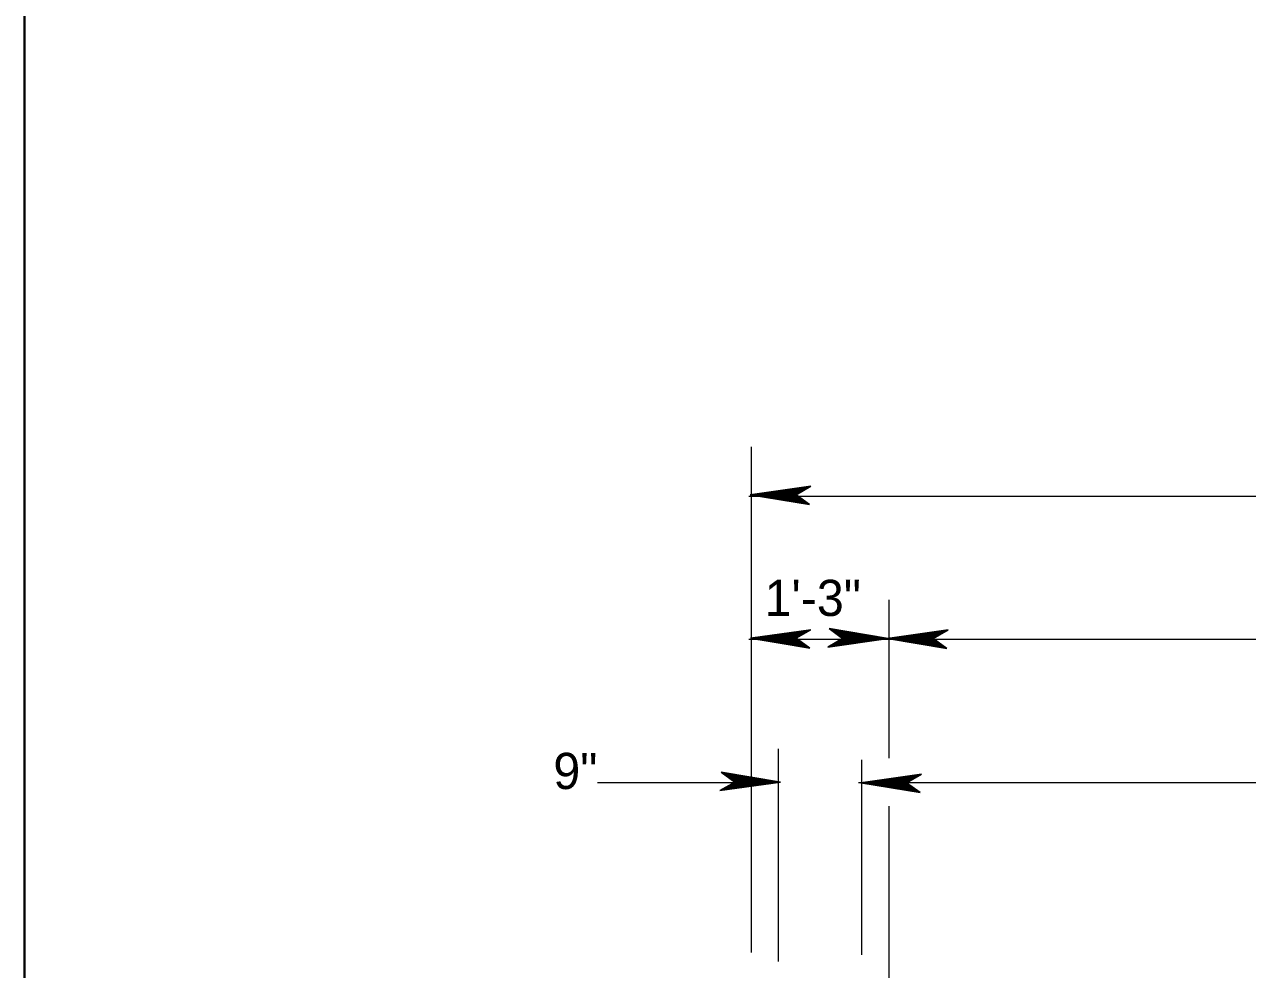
# Model space of a CAD drawing. Extents: x 144 to 252, y 360 to 425.
# Drawn here: x 149.81 to 160.9, y 379.97 to 388.54 of the extents above; entities that cross this region are included whole.
import ezdxf
from ezdxf.enums import TextEntityAlignment as Align

# ---------------------------------------------------------------- set-up
doc = ezdxf.new("R2010")
doc.units = 0
doc.header["$LTSCALE"] = 0.13
for name, color, linetype, lineweight in [('1', 7, 'Continuous', 40), ('16', 7, 'Continuous', 13), ('3', 7, 'Continuous', 13)]:
    doc.layers.add(name, color=color, linetype=linetype, lineweight=lineweight)

msp = doc.modelspace()

# ---------------------------------------------------------------- linework, layer by layer
at = {"layer": '1', "lineweight": 13}
for p, q in [((156.4041, 380.1236), (156.4041, 382.9759)), ((157.4041, 381.1957), (157.4041, 381.871)), ((156.6476, 381.6627), (155.0067, 381.6627)), ((177.4166, 381.6627), (157.3739, 381.6627)), ((157.4041, 380.7103), (157.4041, 381.1957)), ((157.4041, 380.1021), (157.4041, 381.0482))]:
    msp.add_line(p, q, dxfattribs=at)
at = {"layer": '1'}
msp.add_lwpolyline([(250.3172, 361.9183), (250.3172, 423.9913), (149.8112, 423.9913), (149.8112, 361.9183), (230.3642, 361.9183)], dxfattribs=at)
at = {"layer": '3'}
for p, q in [((156.4041, 382.7622), (156.4041, 384.7079)), ((156.3791, 384.2597), (180.3798, 384.2597)), ((156.9406, 384.3518), (156.3918, 384.2741)), ((156.3918, 384.2741), (156.9295, 384.1848)), ((156.8072, 384.2741), (156.3918, 384.2741)), ((156.9346, 384.3483), (156.4062, 384.2734)), ((156.4062, 384.2734), (156.9262, 384.1872)), ((156.9311, 384.3463), (156.4171, 384.2734)), ((156.4171, 384.2734), (156.923, 384.1895)), ((156.9265, 384.3437), (156.4315, 384.2734)), ((156.4315, 384.2734), (156.9187, 384.1927)), ((156.9224, 384.3413), (156.4442, 384.2734)), ((156.9224, 384.3413), (156.4442, 384.2734)), ((156.4442, 384.2734), (156.915, 384.1953)), ((156.9187, 384.3391), (156.4556, 384.2734)), ((156.4556, 384.2734), (156.9117, 384.1977)), ((156.9142, 384.3364), (156.47, 384.2734)), ((156.47, 384.2734), (156.9074, 384.2009)), ((156.9101, 384.334), (156.4827, 384.2734)), ((156.4827, 384.2734), (156.9037, 384.2037)), ((156.9057, 384.3315), (156.4965, 384.2734)), ((156.4965, 384.2734), (156.8996, 384.2066)), ((156.9013, 384.3289), (156.5103, 384.2734)), ((156.5103, 384.2734), (156.8955, 384.2096)), ((156.897, 384.3264), (156.5236, 384.2734)), ((156.5236, 384.2734), (156.8916, 384.2124)), ((156.8925, 384.3237), (156.5375, 384.2734)), ((156.5375, 384.2734), (156.8875, 384.2154)), ((156.8885, 384.3215), (156.5501, 384.2734)), ((156.5501, 384.2734), (156.8837, 384.2181)), ((156.8847, 384.3193), (156.5615, 384.2734)), ((156.5615, 384.2734), (156.8803, 384.2206)), ((156.8798, 384.3164), (156.5772, 384.2734)), ((156.5772, 384.2734), (156.8757, 384.2239)), ((156.8753, 384.3137), (156.591, 384.2734)), ((156.591, 384.2734), (156.8717, 384.2269)), ((156.8682, 384.3096), (156.609, 384.2729)), ((156.609, 384.2729), (156.8674, 384.23)), ((156.8713, 384.3115), (156.6106, 384.2745)), ((156.8637, 384.307), (156.6229, 384.2729)), ((156.6229, 384.2729), (156.8632, 384.233)), ((156.8595, 384.3045), (156.6361, 384.2729)), ((156.6361, 384.2729), (156.8594, 384.2358)), ((156.858, 384.3037), (156.6452, 384.2734)), ((156.6452, 384.2734), (156.8557, 384.2386)), ((156.8541, 384.3014), (156.6572, 384.2734)), ((156.6572, 384.2734), (156.8521, 384.2412)), ((156.8497, 384.2987), (156.671, 384.2734)), ((156.671, 384.2734), (156.848, 384.2442)), ((156.8447, 384.2959), (156.6867, 384.2734)), ((156.6867, 384.2734), (156.8433, 384.2474)), ((156.8406, 384.2935), (156.6993, 384.2734)), ((156.6993, 384.2734), (156.8397, 384.2502)), ((156.8363, 384.291), (156.7125, 384.2734)), ((156.7125, 384.2734), (156.8357, 384.253)), ((156.8325, 384.2887), (156.7245, 384.2734)), ((156.7245, 384.2734), (156.8322, 384.2557)), ((156.8278, 384.2861), (156.739, 384.2734)), ((156.739, 384.2734), (156.8279, 384.2587)), ((156.8234, 384.2835), (156.7528, 384.2734)), ((156.7528, 384.2734), (156.8237, 384.2617)), ((156.8193, 384.2812), (156.7655, 384.2734)), ((156.7655, 384.2734), (156.8201, 384.2644)), ((156.7788, 384.2734), (156.8162, 384.2672)), ((156.8141, 384.2781), (156.789, 384.2745)), ((156.8114, 384.2765), (156.7902, 384.2734)), ((156.7902, 384.2734), (156.8127, 384.2697)), ((156.8003, 384.2734), (156.8098, 384.2719)), ((156.807, 384.2739), (156.9406, 384.3518)), ((156.9295, 384.1848), (156.807, 384.2739)), ((156.4041, 382.7622), (156.4041, 383.3206)), ((157.6499, 382.7622), (157.6499, 383.3206)), ((156.9417, 383.0497), (156.393, 382.972)), ((156.9357, 383.0462), (156.4074, 382.9713)), ((156.9322, 383.0442), (156.4183, 382.9713)), ((156.9277, 383.0416), (156.4327, 382.9713)), ((156.9236, 383.0392), (156.4454, 382.9713)), ((156.9236, 383.0392), (156.4454, 382.9713)), ((156.9199, 383.037), (156.4567, 382.9713)), ((156.9153, 383.0343), (156.4712, 382.9713)), ((156.9112, 383.0319), (156.4839, 382.9713)), ((156.9068, 383.0294), (156.4977, 382.9713)), ((156.9024, 383.0268), (156.5115, 382.9713)), ((156.8082, 382.9718), (156.9417, 383.0497)), ((157.6437, 382.9702), (157.1061, 383.0595)), ((157.1061, 383.0595), (157.2286, 382.9704)), ((157.6293, 382.9709), (157.1093, 383.0572)), ((157.6185, 382.9709), (157.1126, 383.0548)), ((157.6041, 382.9709), (157.1168, 383.0517)), ((157.5913, 382.9709), (157.1206, 383.049)), ((157.58, 382.9709), (157.1239, 383.0466)), ((157.5656, 382.9709), (157.1282, 383.0434)), ((157.5528, 382.9709), (157.1319, 383.0407)), ((157.5391, 382.9709), (157.136, 383.0377)), ((157.5252, 382.9709), (157.1401, 383.0347)), ((157.512, 382.9709), (157.144, 383.0319)), ((157.4981, 382.9709), (157.1481, 383.0289)), ((157.4855, 382.9709), (157.1518, 383.0263)), ((158.1851, 383.048), (157.6363, 382.9702)), ((158.1791, 383.0445), (157.6507, 382.9696)), ((158.1756, 383.0425), (157.6616, 382.9696)), ((158.171, 383.0398), (157.676, 382.9696)), ((158.1669, 383.0374), (157.6887, 382.9696)), ((158.1669, 383.0374), (157.6887, 382.9696)), ((158.1633, 383.0352), (157.7001, 382.9696)), ((158.1587, 383.0326), (157.7145, 382.9696)), ((158.1546, 383.0302), (157.7272, 382.9696)), ((158.1502, 383.0277), (157.741, 382.9696)), ((158.0515, 382.9701), (158.1851, 383.048)), ((156.38, 382.9646), (179.0847, 382.9646)), ((156.393, 382.972), (156.9307, 382.8827)), ((156.8084, 382.972), (156.393, 382.972)), ((156.4074, 382.9713), (156.9274, 382.8851)), ((156.4183, 382.9713), (156.9242, 382.8874)), ((156.4327, 382.9713), (156.9199, 382.8906)), ((156.4454, 382.9713), (156.9162, 382.8932)), ((156.4567, 382.9713), (156.9128, 382.8957)), ((156.4712, 382.9713), (156.9086, 382.8988)), ((156.4839, 382.9713), (156.9048, 382.9016)), ((156.4977, 382.9713), (156.9007, 382.9045)), ((156.5115, 382.9713), (156.8967, 382.9075)), ((156.8982, 383.0243), (156.5247, 382.9713)), ((156.5247, 382.9713), (156.8928, 382.9103)), ((156.8937, 383.0217), (156.5387, 382.9713)), ((156.5387, 382.9713), (156.8887, 382.9133)), ((156.8897, 383.0194), (156.5512, 382.9713)), ((156.5512, 382.9713), (156.8849, 382.916)), ((156.8859, 383.0172), (156.5627, 382.9713)), ((156.5627, 382.9713), (156.8815, 382.9185)), ((156.8809, 383.0143), (156.5783, 382.9713)), ((156.5783, 382.9713), (156.8769, 382.9218)), ((156.8765, 383.0117), (156.5922, 382.9713)), ((156.5922, 382.9713), (156.8728, 382.9248)), ((156.8693, 383.0075), (156.6102, 382.9708)), ((156.6102, 382.9708), (156.8686, 382.9279)), ((156.8725, 383.0094), (156.6118, 382.9724)), ((156.8649, 383.0049), (156.6241, 382.9708)), ((156.6241, 382.9708), (156.8644, 382.9309)), ((156.8607, 383.0024), (156.6372, 382.9708)), ((156.6372, 382.9708), (156.8606, 382.9337)), ((156.8592, 383.0016), (156.6463, 382.9713)), ((156.6463, 382.9713), (156.8568, 382.9365)), ((156.8552, 382.9993), (156.6583, 382.9713)), ((156.6583, 382.9713), (156.8533, 382.9391)), ((156.8508, 382.9967), (156.6722, 382.9713)), ((156.6722, 382.9713), (156.8492, 382.9421)), ((156.8458, 382.9938), (156.6878, 382.9713)), ((156.6878, 382.9713), (156.8445, 382.9453)), ((156.8417, 382.9914), (156.7004, 382.9713)), ((156.7004, 382.9713), (156.8408, 382.9481)), ((156.8375, 382.9889), (156.7137, 382.9713)), ((156.7137, 382.9713), (156.8369, 382.9509)), ((156.8337, 382.9867), (156.7257, 382.9713)), ((156.7257, 382.9713), (156.8333, 382.9536)), ((156.829, 382.984), (156.7402, 382.9713)), ((156.7402, 382.9713), (156.8291, 382.9566)), ((156.8246, 382.9814), (156.754, 382.9713)), ((156.754, 382.9713), (156.8249, 382.9596)), ((156.8205, 382.9791), (156.7667, 382.9713)), ((156.7667, 382.9713), (156.8212, 382.9623)), ((156.7799, 382.9713), (156.8173, 382.9652)), ((156.8152, 382.976), (156.7902, 382.9724)), ((156.8126, 382.9744), (156.7913, 382.9713)), ((156.7913, 382.9713), (156.8139, 382.9676)), ((156.8015, 382.9713), (156.8109, 382.9698)), ((156.9307, 382.8827), (156.8082, 382.9718)), ((157.2286, 382.9704), (157.095, 382.8925)), ((157.095, 382.8925), (157.6437, 382.9702)), ((157.101, 382.896), (157.6293, 382.9709)), ((157.1045, 382.898), (157.6185, 382.9709)), ((157.1091, 382.9007), (157.6041, 382.9709)), ((157.1132, 382.9031), (157.5913, 382.9709)), ((157.1132, 382.9031), (157.5913, 382.9709)), ((157.1168, 382.9052), (157.58, 382.9709)), ((157.1214, 382.9079), (157.5656, 382.9709)), ((157.1255, 382.9103), (157.5528, 382.9709)), ((157.1299, 382.9128), (157.5391, 382.9709)), ((157.1343, 382.9154), (157.5252, 382.9709)), ((157.1386, 382.9179), (157.512, 382.9709)), ((157.1431, 382.9206), (157.4981, 382.9709)), ((157.1471, 382.9228), (157.4855, 382.9709)), ((157.1508, 382.9251), (157.4741, 382.9709)), ((157.4741, 382.9709), (157.1552, 383.0238)), ((157.1558, 382.9279), (157.4584, 382.9709)), ((157.4584, 382.9709), (157.1598, 383.0204)), ((157.1602, 382.9306), (157.4446, 382.9709)), ((157.4446, 382.9709), (157.1639, 383.0174)), ((157.1642, 382.9328), (157.425, 382.9698)), ((157.1674, 382.9348), (157.4266, 382.9714)), ((157.4266, 382.9714), (157.1682, 383.0143)), ((157.1718, 382.9373), (157.4127, 382.9714)), ((157.4127, 382.9714), (157.1723, 383.0113)), ((157.1761, 382.9398), (157.3995, 382.9714)), ((157.3995, 382.9714), (157.1762, 383.0085)), ((157.1776, 382.9407), (157.3904, 382.9709)), ((157.3904, 382.9709), (157.1799, 383.0057)), ((157.1815, 382.9429), (157.3784, 382.9709)), ((157.3784, 382.9709), (157.1835, 383.0032)), ((157.1859, 382.9456), (157.3646, 382.9709)), ((157.3646, 382.9709), (157.1876, 383.0002)), ((157.1909, 382.9484), (157.3489, 382.9709)), ((157.3489, 382.9709), (157.1923, 382.9969)), ((157.195, 382.9508), (157.3363, 382.9709)), ((157.3363, 382.9709), (157.1959, 382.9942)), ((157.1993, 382.9533), (157.3231, 382.9709)), ((157.3231, 382.9709), (157.1998, 382.9913)), ((157.2031, 382.9556), (157.3111, 382.9709)), ((157.3111, 382.9709), (157.2034, 382.9887)), ((157.2966, 382.9709), (157.2077, 382.9857)), ((157.2078, 382.9582), (157.2966, 382.9709)), ((157.2827, 382.9709), (157.2118, 382.9827)), ((157.2122, 382.9608), (157.2827, 382.9709)), ((157.2701, 382.9709), (157.2155, 382.9799)), ((157.2163, 382.9632), (157.2701, 382.9709)), ((157.2568, 382.9709), (157.2194, 382.9771)), ((157.2215, 382.9663), (157.2466, 382.9698)), ((157.2454, 382.9709), (157.2228, 382.9747)), ((157.2242, 382.9678), (157.2454, 382.9709)), ((157.2353, 382.9709), (157.2258, 382.9724)), ((157.2283, 382.9702), (157.6437, 382.9702)), ((157.6363, 382.9702), (158.174, 382.881)), ((158.0517, 382.9702), (157.6363, 382.9702)), ((157.6507, 382.9696), (158.1707, 382.8833)), ((157.6616, 382.9696), (158.1675, 382.8857)), ((157.676, 382.9696), (158.1633, 382.8888)), ((157.6887, 382.9696), (158.1595, 382.8915)), ((157.7001, 382.9696), (158.1562, 382.8939)), ((157.7145, 382.9696), (158.1519, 382.8971)), ((157.7272, 382.9696), (158.1482, 382.8998)), ((157.741, 382.9696), (158.1441, 382.9027)), ((158.1457, 383.0251), (157.7548, 382.9696)), ((157.7548, 382.9696), (158.14, 382.9058)), ((158.1415, 383.0226), (157.7681, 382.9696)), ((157.7681, 382.9696), (158.1361, 382.9086)), ((158.137, 383.0199), (157.782, 382.9696)), ((157.782, 382.9696), (158.132, 382.9116)), ((158.133, 383.0177), (157.7946, 382.9696)), ((157.7946, 382.9696), (158.1283, 382.9142)), ((158.1292, 383.0154), (157.806, 382.9696)), ((157.806, 382.9696), (158.1248, 382.9167)), ((158.1242, 383.0126), (157.8217, 382.9696)), ((157.8217, 382.9696), (158.1202, 382.9201)), ((158.1198, 383.0099), (157.8355, 382.9696)), ((157.8355, 382.9696), (158.1162, 382.9231)), ((158.1127, 383.0057), (157.8535, 382.9691)), ((157.8535, 382.9691), (158.1119, 382.9262)), ((158.1158, 383.0077), (157.8551, 382.9707)), ((158.1082, 383.0032), (157.8674, 382.9691)), ((157.8674, 382.9691), (158.1077, 382.9292)), ((158.104, 383.0007), (157.8806, 382.9691)), ((157.8806, 382.9691), (158.1039, 382.932)), ((158.1025, 382.9998), (157.8897, 382.9696)), ((157.8897, 382.9696), (158.1002, 382.9348)), ((158.0986, 382.9976), (157.9017, 382.9696)), ((157.9017, 382.9696), (158.0966, 382.9373)), ((158.0942, 382.9949), (157.9155, 382.9696)), ((157.9155, 382.9696), (158.0925, 382.9403)), ((158.0892, 382.9921), (157.9312, 382.9696)), ((157.9312, 382.9696), (158.0878, 382.9436)), ((158.0851, 382.9897), (157.9437, 382.9696)), ((157.9437, 382.9696), (158.0842, 382.9463)), ((158.0808, 382.9872), (157.957, 382.9696)), ((157.957, 382.9696), (158.0803, 382.9492)), ((158.077, 382.9849), (157.969, 382.9696)), ((157.969, 382.9696), (158.0767, 382.9518)), ((158.0723, 382.9822), (157.9835, 382.9696)), ((157.9835, 382.9696), (158.0724, 382.9548)), ((158.0679, 382.9797), (157.9973, 382.9696)), ((157.9973, 382.9696), (158.0683, 382.9578)), ((158.0638, 382.9773), (158.01, 382.9696)), ((158.01, 382.9696), (158.0646, 382.9606)), ((158.0232, 382.9696), (158.0607, 382.9634)), ((158.0586, 382.9742), (158.0335, 382.9707)), ((158.0559, 382.9727), (158.0347, 382.9696)), ((158.0347, 382.9696), (158.0572, 382.9658)), ((158.0448, 382.9696), (158.0542, 382.9681)), ((158.174, 382.881), (158.0515, 382.9701)), ((156.4041, 382.7622), (156.4041, 382.8667)), ((156.4041, 382.7137), (156.4041, 382.8667)), ((157.6499, 381.8838), (157.6499, 382.8667)), ((156.648, 380.0423), (156.648, 381.9688)), ((156.6659, 381.6682), (156.1283, 381.7574)), ((156.1283, 381.7574), (156.2507, 381.6683)), ((156.6515, 381.6688), (156.1315, 381.7551)), ((156.6407, 381.6688), (156.1347, 381.7527)), ((156.6262, 381.6688), (156.139, 381.7496)), ((156.6135, 381.6688), (156.1428, 381.7469)), ((156.6022, 381.6688), (156.1461, 381.7445)), ((156.5877, 381.6688), (156.1503, 381.7413)), ((156.575, 381.6688), (156.1541, 381.7386)), ((156.5613, 381.6688), (156.1582, 381.7357)), ((156.5474, 381.6688), (156.1623, 381.7327)), ((156.5342, 381.6688), (156.1662, 381.7298)), ((156.5203, 381.6688), (156.1702, 381.7268)), ((156.5077, 381.6688), (156.174, 381.7242)), ((156.4963, 381.6688), (156.1774, 381.7217)), ((156.4806, 381.6688), (156.182, 381.7183)), ((156.4667, 381.6688), (156.1861, 381.7153)), ((156.4487, 381.6693), (156.1903, 381.7122)), ((156.4348, 381.6693), (156.1945, 381.7092)), ((156.4217, 381.6693), (156.1983, 381.7064)), ((156.4126, 381.6688), (156.2021, 381.7037)), ((156.4006, 381.6688), (156.2057, 381.7011)), ((156.3868, 381.6688), (156.2097, 381.6981)), ((156.3711, 381.6688), (156.2144, 381.6948)), ((157.943, 381.7406), (157.3942, 381.6628)), ((157.937, 381.7371), (157.4087, 381.6622)), ((157.9335, 381.7351), (157.4195, 381.6622)), ((157.9289, 381.7324), (157.4339, 381.6622)), ((157.9248, 381.73), (157.4467, 381.6622)), ((157.9248, 381.73), (157.4467, 381.6622)), ((157.9212, 381.7278), (157.458, 381.6622)), ((157.9166, 381.7252), (157.4724, 381.6622)), ((157.9125, 381.7227), (157.4852, 381.6622)), ((157.9081, 381.7202), (157.4989, 381.6622)), ((157.9037, 381.7177), (157.5127, 381.6622)), ((157.8994, 381.7152), (157.526, 381.6622)), ((157.8949, 381.7125), (157.5399, 381.6622)), ((157.8909, 381.7102), (157.5525, 381.6622)), ((157.8872, 381.708), (157.5639, 381.6622)), ((157.8822, 381.7052), (157.5796, 381.6622)), ((157.8777, 381.7025), (157.5934, 381.6622)), ((157.8706, 381.6983), (157.6114, 381.6617)), ((157.8738, 381.7002), (157.613, 381.6633)), ((157.8662, 381.6957), (157.6253, 381.6617)), ((157.8094, 381.6627), (157.943, 381.7406)), ((156.2507, 381.6683), (156.1172, 381.5904)), ((156.1172, 381.5904), (156.6659, 381.6682)), ((156.1232, 381.5939), (156.6515, 381.6688)), ((156.1267, 381.5959), (156.6407, 381.6688)), ((156.1312, 381.5986), (156.6262, 381.6688)), ((156.1353, 381.601), (156.6135, 381.6688)), ((156.1353, 381.601), (156.6135, 381.6688)), ((156.139, 381.6032), (156.6022, 381.6688)), ((156.1436, 381.6058), (156.5877, 381.6688)), ((156.1477, 381.6082), (156.575, 381.6688)), ((156.1521, 381.6107), (156.5613, 381.6688)), ((156.1565, 381.6133), (156.5474, 381.6688)), ((156.1608, 381.6158), (156.5342, 381.6688)), ((156.1652, 381.6185), (156.5203, 381.6688)), ((156.1693, 381.6207), (156.5077, 381.6688)), ((156.173, 381.623), (156.4963, 381.6688)), ((156.178, 381.6258), (156.4806, 381.6688)), ((156.1824, 381.6285), (156.4667, 381.6688)), ((156.1864, 381.6307), (156.4472, 381.6678)), ((156.1896, 381.6327), (156.4487, 381.6693)), ((156.194, 381.6352), (156.4348, 381.6693)), ((156.1983, 381.6377), (156.4217, 381.6693)), ((156.1997, 381.6386), (156.4126, 381.6688)), ((156.2037, 381.6408), (156.4006, 381.6688)), ((156.2081, 381.6435), (156.3868, 381.6688)), ((156.2131, 381.6463), (156.3711, 381.6688)), ((156.2172, 381.6488), (156.3585, 381.6688)), ((156.3585, 381.6688), (156.2181, 381.6921)), ((156.2214, 381.6513), (156.3452, 381.6688)), ((156.3452, 381.6688), (156.222, 381.6893)), ((156.2252, 381.6535), (156.3332, 381.6688)), ((156.3332, 381.6688), (156.2256, 381.6866)), ((156.3187, 381.6688), (156.2298, 381.6836)), ((156.2299, 381.6562), (156.3187, 381.6688)), ((156.3049, 381.6688), (156.234, 381.6806)), ((156.2343, 381.6587), (156.3049, 381.6688)), ((156.2922, 381.6688), (156.2377, 381.6778)), ((156.2384, 381.6611), (156.2922, 381.6688)), ((156.279, 381.6688), (156.2416, 381.675)), ((156.2437, 381.6642), (156.2687, 381.6678)), ((156.2676, 381.6688), (156.245, 381.6726)), ((156.2463, 381.6658), (156.2676, 381.6688)), ((156.2574, 381.6688), (156.248, 381.6703)), ((156.2505, 381.6682), (156.6659, 381.6682)), ((157.3942, 381.6628), (157.9319, 381.5736)), ((157.8097, 381.6628), (157.3942, 381.6628)), ((157.4087, 381.6622), (157.9287, 381.5759)), ((157.4195, 381.6622), (157.9254, 381.5782)), ((157.4339, 381.6622), (157.9212, 381.5814)), ((157.4467, 381.6622), (157.9174, 381.5841)), ((157.458, 381.6622), (157.9141, 381.5865)), ((157.4724, 381.6622), (157.9098, 381.5897)), ((157.4852, 381.6622), (157.9061, 381.5924)), ((157.4989, 381.6622), (157.902, 381.5953)), ((157.5127, 381.6622), (157.8979, 381.5983)), ((157.526, 381.6622), (157.894, 381.6012)), ((157.5399, 381.6622), (157.8899, 381.6042)), ((157.5525, 381.6622), (157.8862, 381.6068)), ((157.5639, 381.6622), (157.8827, 381.6093)), ((157.5796, 381.6622), (157.8782, 381.6127)), ((157.5934, 381.6622), (157.8741, 381.6157)), ((157.6114, 381.6617), (157.8698, 381.6187)), ((157.6253, 381.6617), (157.8657, 381.6217)), ((157.8619, 381.6932), (157.6385, 381.6617)), ((157.6385, 381.6617), (157.8618, 381.6246)), ((157.8604, 381.6924), (157.6476, 381.6622)), ((157.6476, 381.6622), (157.8581, 381.6273)), ((157.8565, 381.6902), (157.6596, 381.6622)), ((157.6596, 381.6622), (157.8545, 381.6299)), ((157.8521, 381.6875), (157.6734, 381.6622)), ((157.6734, 381.6622), (157.8504, 381.6329)), ((157.8471, 381.6847), (157.6891, 381.6622)), ((157.6891, 381.6622), (157.8457, 381.6362)), ((157.843, 381.6823), (157.7017, 381.6622)), ((157.7017, 381.6622), (157.8421, 381.6389)), ((157.8388, 381.6798), (157.7149, 381.6622)), ((157.7149, 381.6622), (157.8382, 381.6418)), ((157.8349, 381.6775), (157.7269, 381.6622)), ((157.7269, 381.6622), (157.8346, 381.6444)), ((157.8303, 381.6748), (157.7414, 381.6622)), ((157.7414, 381.6622), (157.8303, 381.6474)), ((157.8258, 381.6722), (157.7552, 381.6622)), ((157.7552, 381.6622), (157.8262, 381.6504)), ((157.8218, 381.6699), (157.7679, 381.6622)), ((157.7679, 381.6622), (157.8225, 381.6532)), ((157.7812, 381.6622), (157.8186, 381.656)), ((157.8165, 381.6668), (157.7914, 381.6633)), ((157.8138, 381.6653), (157.7926, 381.6622)), ((157.7926, 381.6622), (157.8152, 381.6584)), ((157.8028, 381.6622), (157.8122, 381.6607)), ((157.9319, 381.5736), (157.8094, 381.6627)), ((156.4041, 380.5688), (156.4041, 381.5673)), ((156.4041, 380.5688), (156.4041, 381.5269)), ((157.6499, 381.1829), (157.6499, 381.4505)), ((157.6499, 380.781), (157.6499, 381.1829)), ((157.6499, 378.7893), (157.6499, 381.0482))]:
    msp.add_line(p, q, dxfattribs=at)

# ---------------------------------------------------------------- texts
at = {"layer": '16'}
msp.add_text('1\'-3"', height=0.3281, dxfattribs=at).set_placement((156.9586, 383.1745), align=Align.CENTER)
msp.add_text('9"', height=0.3281, dxfattribs=at).set_placement((154.6063, 381.6053))

doc.saveas('drawing.dxf')
